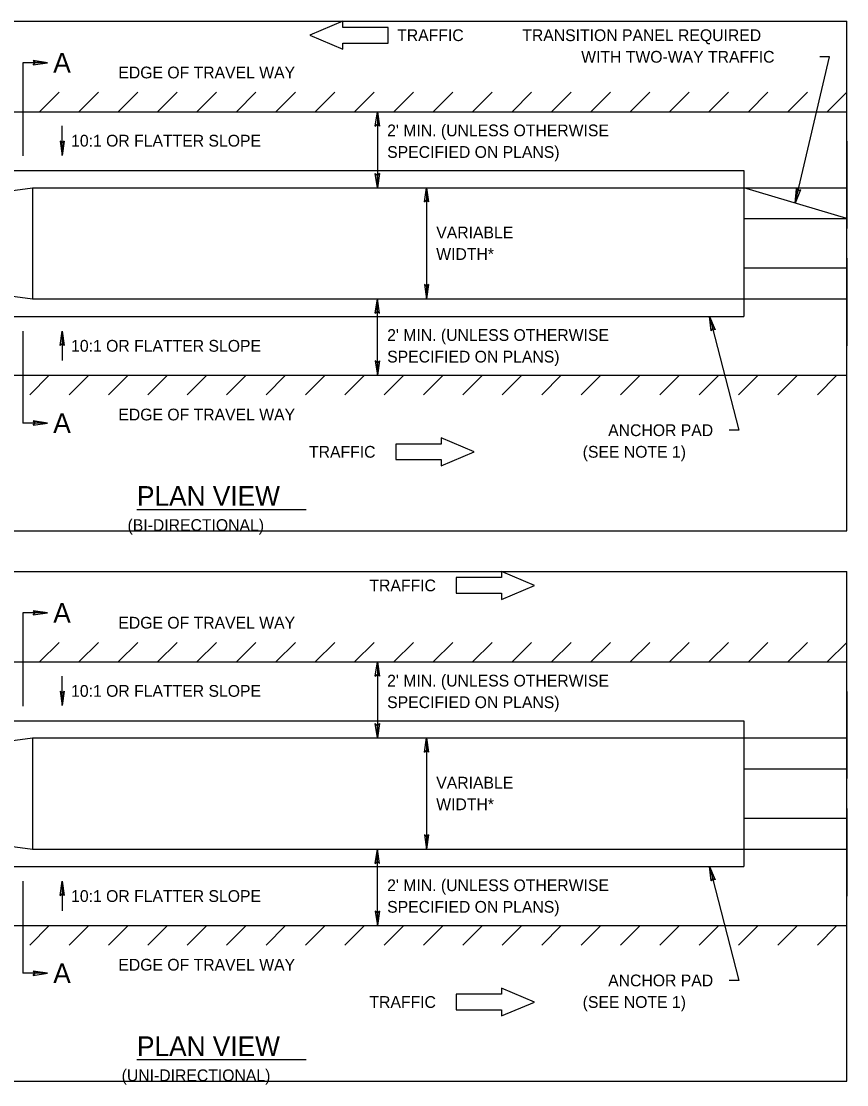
# Model space of a CAD drawing. Extents: x 12.3 to 19.6, y 6 to 16.1.
# Drawn here: x 15.05 to 19.25, y 10.66 to 16.08 of the extents above; entities that cross this region are included whole.
import ezdxf

# ---------------------------------------------------------------- set-up
doc = ezdxf.new("R2010")
doc.units = 0
for name, color, linetype in [('Default', 7, 'Continuous'), ('DETL-DIMS', 7, 'Continuous'), ('DETL-LINE', 7, 'Continuous'), ('DETL-NOTE', 7, 'Continuous'), ('DETL-TITL', 7, 'Continuous')]:
    doc.layers.add(name, color=color, linetype=linetype)

msp = doc.modelspace()

# ---------------------------------------------------------------- linework, layer by layer
at = {"layer": 'Default'}
for p, q in [((12.6137, 16.0809), (19.2537, 16.0809)), ((19.2537, 13.4842), (19.2537, 16.0809)), ((12.6137, 13.4842), (19.2537, 13.4842)), ((12.6137, 13.2777), (19.2537, 13.2777)), ((19.2537, 10.6809), (19.2537, 13.2777)), ((12.6137, 10.6809), (19.2537, 10.6809))]:
    msp.add_line(p, q, dxfattribs=at)
at = {"layer": 'DETL-DIMS'}
for p, q in [((15.1081, 15.8805), (15.181, 15.8699)), ((15.1081, 15.8805), (15.1172, 15.8699)), ((18.9915, 15.1544), (19.1665, 15.8999)), ((19.1665, 15.8999), (19.1165, 15.8999)), ((15.181, 15.8699), (15.056, 15.8699)), ((15.056, 15.8699), (15.056, 15.3949)), ((15.1081, 15.8593), (15.181, 15.8699)), ((15.1081, 15.8593), (15.1172, 15.8699)), ((16.8516, 15.547), (16.8622, 15.6199)), ((16.8622, 15.6199), (16.8622, 15.2331)), ((16.8728, 15.547), (16.8622, 15.6199)), ((16.8516, 15.547), (16.8622, 15.5561)), ((16.8728, 15.547), (16.8622, 15.5561)), ((15.256, 15.3975), (15.256, 15.5475)), ((15.2454, 15.4704), (15.256, 15.3975)), ((15.2454, 15.4704), (15.256, 15.4613)), ((15.2666, 15.4704), (15.256, 15.3975)), ((15.2666, 15.4704), (15.256, 15.4613)), ((16.8516, 15.306), (16.8622, 15.2331)), ((16.8516, 15.306), (16.8622, 15.2969)), ((16.8728, 15.306), (16.8622, 15.2331)), ((16.8728, 15.306), (16.8622, 15.2969)), ((17.1016, 15.1602), (17.1122, 15.2331)), ((17.1122, 15.2331), (17.1122, 14.6669)), ((17.1228, 15.1602), (17.1122, 15.2331)), ((18.9978, 15.2278), (18.9915, 15.1544)), ((18.9978, 15.2278), (19.0061, 15.2165)), ((19.0185, 15.2229), (18.9915, 15.1544)), ((19.0185, 15.2229), (19.0061, 15.2165)), ((17.1016, 15.1602), (17.1122, 15.1693)), ((17.1228, 15.1602), (17.1122, 15.1693)), ((17.1016, 14.7398), (17.1122, 14.6669)), ((17.1016, 14.7398), (17.1122, 14.7307)), ((17.1228, 14.7398), (17.1122, 14.6669)), ((17.1228, 14.7398), (17.1122, 14.7307)), ((16.8516, 14.594), (16.8622, 14.6669)), ((16.8728, 14.594), (16.8622, 14.6669)), ((16.8622, 14.2774), (16.8622, 14.6669)), ((16.8516, 14.594), (16.8622, 14.6031)), ((16.8728, 14.594), (16.8622, 14.6031)), ((18.5543, 14.5774), (18.7043, 13.9974)), ((18.5828, 14.5095), (18.5543, 14.5774)), ((18.5623, 14.5042), (18.5543, 14.5774)), ((15.056, 14.5024), (15.056, 14.0341)), ((15.2454, 14.4295), (15.256, 14.5024)), ((15.2666, 14.4295), (15.256, 14.5024)), ((15.256, 14.5024), (15.256, 14.3524)), ((18.5623, 14.5042), (18.5702, 14.5157)), ((18.5828, 14.5095), (18.5702, 14.5157)), ((15.2454, 14.4295), (15.256, 14.4386)), ((15.2666, 14.4295), (15.256, 14.4386)), ((16.8516, 14.3503), (16.8622, 14.2774)), ((16.8516, 14.3503), (16.8622, 14.3412)), ((16.8728, 14.3503), (16.8622, 14.2774)), ((16.8728, 14.3503), (16.8622, 14.3412)), ((15.181, 14.0341), (15.056, 14.0341)), ((15.1081, 14.0447), (15.181, 14.0341)), ((15.1081, 14.0447), (15.1172, 14.0341)), ((15.1081, 14.0235), (15.181, 14.0341)), ((15.1081, 14.0235), (15.1172, 14.0341)), ((18.7043, 13.9974), (18.6543, 13.9974)), ((15.181, 13.0667), (15.056, 13.0667)), ((15.056, 13.0667), (15.056, 12.5917)), ((15.1081, 13.0773), (15.181, 13.0667)), ((15.1081, 13.0773), (15.1172, 13.0667)), ((15.1081, 13.0561), (15.181, 13.0667)), ((15.1081, 13.0561), (15.1172, 13.0667)), ((16.8516, 12.7438), (16.8622, 12.8167)), ((16.8622, 12.8167), (16.8622, 12.4298)), ((16.8728, 12.7438), (16.8622, 12.8167)), ((15.256, 12.5943), (15.256, 12.7443)), ((16.8516, 12.7438), (16.8622, 12.7529)), ((16.8728, 12.7438), (16.8622, 12.7529)), ((15.2454, 12.6672), (15.256, 12.5943)), ((15.2454, 12.6672), (15.256, 12.6581)), ((15.2666, 12.6672), (15.256, 12.5943)), ((15.2666, 12.6672), (15.256, 12.6581)), ((16.8516, 12.5027), (16.8622, 12.4298)), ((16.8516, 12.5027), (16.8622, 12.4936)), ((16.8728, 12.5027), (16.8622, 12.4298)), ((16.8728, 12.5027), (16.8622, 12.4936)), ((17.1016, 12.3569), (17.1122, 12.4298)), ((17.1122, 12.4298), (17.1122, 11.8636)), ((17.1228, 12.3569), (17.1122, 12.4298)), ((17.1016, 12.3569), (17.1122, 12.366)), ((17.1228, 12.3569), (17.1122, 12.366)), ((17.1016, 11.9365), (17.1122, 11.8636)), ((17.1016, 11.9365), (17.1122, 11.9274)), ((17.1228, 11.9365), (17.1122, 11.8636)), ((17.1228, 11.9365), (17.1122, 11.9274)), ((16.8516, 11.7907), (16.8622, 11.8636)), ((16.8728, 11.7907), (16.8622, 11.8636)), ((16.8622, 11.4742), (16.8622, 11.8636)), ((16.8516, 11.7907), (16.8622, 11.7998)), ((16.8728, 11.7907), (16.8622, 11.7998)), ((18.5543, 11.7742), (18.7043, 11.1942)), ((18.5828, 11.7062), (18.5543, 11.7742)), ((18.5623, 11.7009), (18.5543, 11.7742)), ((18.5623, 11.7009), (18.5702, 11.7124)), ((18.5828, 11.7062), (18.5702, 11.7124)), ((15.056, 11.6992), (15.056, 11.2308)), ((15.2454, 11.6263), (15.256, 11.6992)), ((15.2666, 11.6263), (15.256, 11.6992)), ((15.256, 11.6992), (15.256, 11.5492)), ((15.2454, 11.6263), (15.256, 11.6354)), ((15.2666, 11.6263), (15.256, 11.6354)), ((16.8516, 11.5471), (16.8622, 11.4742)), ((16.8516, 11.5471), (16.8622, 11.538)), ((16.8728, 11.5471), (16.8622, 11.4742)), ((16.8728, 11.5471), (16.8622, 11.538)), ((15.181, 11.2308), (15.056, 11.2308)), ((15.1081, 11.2414), (15.181, 11.2308)), ((15.1081, 11.2414), (15.1172, 11.2308)), ((15.1081, 11.2202), (15.181, 11.2308)), ((15.1081, 11.2202), (15.1172, 11.2308)), ((18.7043, 11.1942), (18.6543, 11.1942))]:
    msp.add_line(p, q, dxfattribs=at)
for points in [[(16.9175, 16.0497), (16.686, 16.0497), (16.686, 16.0809), (16.5183, 16.0099), (16.686, 15.9389), (16.686, 15.9701), (16.9175, 15.9701), (16.9175, 16.0497)], [(16.9556, 13.8476), (17.1871, 13.8476), (17.1871, 13.8164), (17.3548, 13.8874), (17.1871, 13.9584), (17.1871, 13.9272), (16.9556, 13.9272), (16.9556, 13.8476)], [(17.2634, 13.1669), (17.4949, 13.1669), (17.4949, 13.1357), (17.6626, 13.2067), (17.4949, 13.2777), (17.4949, 13.2465), (17.2634, 13.2465), (17.2634, 13.1669)], [(17.2634, 11.0444), (17.4949, 11.0444), (17.4949, 11.0132), (17.6626, 11.0842), (17.4949, 11.1552), (17.4949, 11.124), (17.2634, 11.124), (17.2634, 11.0444)]]:
    msp.add_lwpolyline(points, dxfattribs=at)
for points in [[(15.1081, 15.8593), (15.181, 15.8699), (15.1081, 15.8805), (15.1172, 15.8699)], [(16.8516, 15.547), (16.8622, 15.6199), (16.8728, 15.547), (16.8622, 15.5561)], [(15.2454, 15.4704), (15.256, 15.3975), (15.2666, 15.4704), (15.256, 15.4613)], [(16.8728, 15.306), (16.8622, 15.2331), (16.8516, 15.306), (16.8622, 15.2969)], [(17.1016, 15.1602), (17.1122, 15.2331), (17.1228, 15.1602), (17.1122, 15.1693)], [(19.0185, 15.2229), (18.9915, 15.1544), (18.9978, 15.2278), (19.0061, 15.2165)], [(17.1016, 14.7398), (17.1122, 14.6669), (17.1228, 14.7398), (17.1122, 14.7307)], [(16.8728, 14.594), (16.8622, 14.6669), (16.8516, 14.594), (16.8622, 14.6031)], [(18.5623, 14.5042), (18.5543, 14.5774), (18.5828, 14.5095), (18.5702, 14.5157)], [(15.2454, 14.4295), (15.256, 14.5024), (15.2666, 14.4295), (15.256, 14.4386)], [(16.8516, 14.3503), (16.8622, 14.2774), (16.8728, 14.3503), (16.8622, 14.3412)], [(15.1081, 14.0235), (15.181, 14.0341), (15.1081, 14.0447), (15.1172, 14.0341)], [(15.1081, 13.0561), (15.181, 13.0667), (15.1081, 13.0773), (15.1172, 13.0667)], [(16.8516, 12.7438), (16.8622, 12.8167), (16.8728, 12.7438), (16.8622, 12.7529)], [(15.2454, 12.6672), (15.256, 12.5943), (15.2666, 12.6672), (15.256, 12.6581)], [(16.8728, 12.5027), (16.8622, 12.4298), (16.8516, 12.5027), (16.8622, 12.4936)], [(17.1016, 12.3569), (17.1122, 12.4298), (17.1228, 12.3569), (17.1122, 12.366)], [(17.1016, 11.9365), (17.1122, 11.8636), (17.1228, 11.9365), (17.1122, 11.9274)], [(16.8728, 11.7907), (16.8622, 11.8636), (16.8516, 11.7907), (16.8622, 11.7998)], [(18.5623, 11.7009), (18.5543, 11.7742), (18.5828, 11.7062), (18.5702, 11.7124)], [(15.2454, 11.6263), (15.256, 11.6992), (15.2666, 11.6263), (15.256, 11.6354)], [(16.8516, 11.5471), (16.8622, 11.4742), (16.8728, 11.5471), (16.8622, 11.538)], [(15.1081, 11.2202), (15.181, 11.2308), (15.1081, 11.2414), (15.1172, 11.2308)]]:
    msp.add_lwpolyline(points, close=True, dxfattribs=at)
at = {"layer": 'DETL-LINE'}
for p, q in [((15.1406, 15.6199), (15.2406, 15.7199)), ((15.3412, 15.6199), (15.4412, 15.7199)), ((15.5419, 15.6199), (15.6419, 15.7199)), ((15.7425, 15.6199), (15.8425, 15.7199)), ((15.9432, 15.6199), (16.0432, 15.7199)), ((16.1439, 15.6199), (16.2439, 15.7199)), ((16.3445, 15.6199), (16.4445, 15.7199)), ((16.5452, 15.6199), (16.6452, 15.7199)), ((16.7458, 15.6199), (16.8458, 15.7199)), ((16.9465, 15.6199), (17.0465, 15.7199)), ((17.1471, 15.6199), (17.2471, 15.7199)), ((17.3478, 15.6199), (17.4478, 15.7199)), ((17.5484, 15.6199), (17.6484, 15.7199)), ((17.7491, 15.6199), (17.8491, 15.7199)), ((17.9498, 15.6199), (18.0498, 15.7199)), ((18.1504, 15.6199), (18.2504, 15.7199)), ((18.3511, 15.6199), (18.4511, 15.7199)), ((18.5517, 15.6199), (18.6517, 15.7199)), ((18.7524, 15.6199), (18.8524, 15.7199)), ((18.953, 15.6199), (19.053, 15.7199)), ((19.1537, 15.6199), (19.2537, 15.7199)), ((12.8837, 15.6199), (19.2537, 15.6199)), ((19.2537, 15.4699), (19.2537, 15.0257)), ((14.4574, 15.3199), (18.7293, 15.3199)), ((18.7293, 15.3199), (18.7293, 14.5774)), ((14.5945, 15.1649), (15.106, 15.2331)), ((15.106, 15.2331), (19.2537, 15.2331)), ((15.106, 15.2331), (15.106, 14.6669)), ((19.2537, 15.0757), (18.7293, 15.2331)), ((18.7293, 15.0757), (19.2537, 15.0757)), ((19.2537, 14.8743), (19.2537, 14.4274)), ((18.7293, 14.8243), (19.2537, 14.8243)), ((14.5945, 14.7351), (15.106, 14.6669)), ((15.106, 14.6669), (19.2537, 14.6669)), ((14.4574, 14.5774), (18.7293, 14.5774)), ((12.8837, 14.2774), (19.2537, 14.2774)), ((15.0909, 14.1774), (15.1909, 14.2774)), ((15.2916, 14.1774), (15.3916, 14.2774)), ((15.4922, 14.1774), (15.5922, 14.2774)), ((15.6929, 14.1774), (15.7929, 14.2774)), ((15.8935, 14.1774), (15.9935, 14.2774)), ((16.0942, 14.1774), (16.1942, 14.2774)), ((16.2949, 14.1774), (16.3949, 14.2774)), ((16.4955, 14.1774), (16.5955, 14.2774)), ((16.6962, 14.1774), (16.7962, 14.2774)), ((16.8968, 14.1774), (16.9968, 14.2774)), ((17.0975, 14.1774), (17.1975, 14.2774)), ((17.2981, 14.1774), (17.3981, 14.2774)), ((17.4988, 14.1774), (17.5988, 14.2774)), ((17.6995, 14.1774), (17.7995, 14.2774)), ((17.9001, 14.1774), (18.0001, 14.2774)), ((18.1008, 14.1774), (18.2008, 14.2774)), ((18.3014, 14.1774), (18.4014, 14.2774)), ((18.5021, 14.1774), (18.6021, 14.2774)), ((18.7027, 14.1774), (18.8027, 14.2774)), ((18.9034, 14.1774), (19.0034, 14.2774)), ((19.1041, 14.1774), (19.2041, 14.2774)), ((15.1406, 12.8167), (15.2406, 12.9167)), ((15.3412, 12.8167), (15.4412, 12.9167)), ((15.5419, 12.8167), (15.6419, 12.9167)), ((15.7425, 12.8167), (15.8425, 12.9167)), ((15.9432, 12.8167), (16.0432, 12.9167)), ((16.1439, 12.8167), (16.2439, 12.9167)), ((16.3445, 12.8167), (16.4445, 12.9167)), ((16.5452, 12.8167), (16.6452, 12.9167)), ((16.7458, 12.8167), (16.8458, 12.9167)), ((16.9465, 12.8167), (17.0465, 12.9167)), ((17.1471, 12.8167), (17.2471, 12.9167)), ((17.3478, 12.8167), (17.4478, 12.9167)), ((17.5484, 12.8167), (17.6484, 12.9167)), ((17.7491, 12.8167), (17.8491, 12.9167)), ((17.9498, 12.8167), (18.0498, 12.9167)), ((18.1504, 12.8167), (18.2504, 12.9167)), ((18.3511, 12.8167), (18.4511, 12.9167)), ((18.5517, 12.8167), (18.6517, 12.9167)), ((18.7524, 12.8167), (18.8524, 12.9167)), ((18.953, 12.8167), (19.053, 12.9167)), ((19.1537, 12.8167), (19.2537, 12.9167)), ((12.8837, 12.8167), (19.2537, 12.8167)), ((19.2537, 12.6667), (19.2537, 12.2224)), ((14.4574, 12.5167), (18.7293, 12.5167)), ((18.7293, 12.5167), (18.7293, 11.7742)), ((14.5945, 12.3616), (15.106, 12.4298)), ((15.106, 12.4298), (19.2537, 12.4298)), ((15.106, 12.4298), (15.106, 11.8636)), ((18.7293, 12.2724), (19.2537, 12.2724)), ((19.2537, 12.071), (19.2537, 11.6242)), ((18.7293, 12.021), (19.2537, 12.021)), ((14.5945, 11.9318), (15.106, 11.8636)), ((15.106, 11.8636), (19.2537, 11.8636)), ((14.4574, 11.7742), (18.7293, 11.7742)), ((12.8837, 11.4742), (19.2537, 11.4742)), ((15.0909, 11.3742), (15.1909, 11.4742)), ((15.2916, 11.3742), (15.3916, 11.4742)), ((15.4922, 11.3742), (15.5922, 11.4742)), ((15.6929, 11.3742), (15.7929, 11.4742)), ((15.8935, 11.3742), (15.9935, 11.4742)), ((16.0942, 11.3742), (16.1942, 11.4742)), ((16.2949, 11.3742), (16.3949, 11.4742)), ((16.4955, 11.3742), (16.5955, 11.4742)), ((16.6962, 11.3742), (16.7962, 11.4742)), ((16.8968, 11.3742), (16.9968, 11.4742)), ((17.0975, 11.3742), (17.1975, 11.4742)), ((17.2981, 11.3742), (17.3981, 11.4742)), ((17.4988, 11.3742), (17.5988, 11.4742)), ((17.6995, 11.3742), (17.7995, 11.4742)), ((17.9001, 11.3742), (18.0001, 11.4742)), ((18.1008, 11.3742), (18.2008, 11.4742)), ((18.3014, 11.3742), (18.4014, 11.4742)), ((18.5021, 11.3742), (18.6021, 11.4742)), ((18.7027, 11.3742), (18.8027, 11.4742)), ((18.9034, 11.3742), (19.0034, 11.4742)), ((19.1041, 11.3742), (19.2041, 11.4742))]:
    msp.add_line(p, q, dxfattribs=at)
at = {"layer": 'DETL-TITL'}
for p, q in [((15.6375, 13.5942), (16.4999, 13.5942)), ((15.6375, 10.7909), (16.4999, 10.7909))]:
    msp.add_line(p, q, dxfattribs=at)

# ---------------------------------------------------------------- texts
at = {"layer": 'DETL-NOTE'}
for s, p in [('TRAFFIC', (16.9633, 15.9799)), ('10:1 OR FLATTER SLOPE', (15.3018, 15.4425)), ('TRAFFIC', (16.5141, 13.8574)), ('TRAFFIC', (16.8219, 13.1767)), ('10:1 OR FLATTER SLOPE', (15.3018, 12.6393)), ('TRAFFIC', (16.8219, 11.0542))]:
    msp.add_text(s, height=0.06, dxfattribs=at).set_placement(p)
for s, p in [('TRANSITION PANEL REQUIRED', (17.6006, 15.9799)), ('WITH TWO-WAY TRAFFIC', (17.9008, 15.8699)), ('EDGE OF TRAVEL WAY', (15.5426, 15.7899)), ("2' MIN. (UNLESS OTHERWISE", (16.9122, 15.4949)), ('SPECIFIED ON PLANS)', (16.9122, 15.3849)), ('VARIABLE', (17.1622, 14.975)), ('WIDTH*', (17.1622, 14.865)), ("2' MIN. (UNLESS OTHERWISE", (16.9122, 14.4524)), ('10:1 OR FLATTER SLOPE', (15.3018, 14.3974)), ('SPECIFIED ON PLANS)', (16.9122, 14.3424)), ('EDGE OF TRAVEL WAY', (15.5426, 14.0474)), ('ANCHOR PAD', (18.0382, 13.9674)), ('(SEE NOTE 1)', (17.9084, 13.8574)), ('(BI-DIRECTIONAL)', (15.5894, 13.4842)), ('EDGE OF TRAVEL WAY', (15.5426, 12.9867)), ("2' MIN. (UNLESS OTHERWISE", (16.9122, 12.6917)), ('SPECIFIED ON PLANS)', (16.9122, 12.5817)), ('VARIABLE', (17.1622, 12.1717)), ('WIDTH*', (17.1622, 12.0617)), ("2' MIN. (UNLESS OTHERWISE", (16.9122, 11.6492)), ('10:1 OR FLATTER SLOPE', (15.3018, 11.5942)), ('SPECIFIED ON PLANS)', (16.9122, 11.5392)), ('EDGE OF TRAVEL WAY', (15.5426, 11.2442)), ('ANCHOR PAD', (18.0382, 11.1642)), ('(SEE NOTE 1)', (17.9084, 11.0542)), ('(UNI-DIRECTIONAL)', (15.5594, 10.6809))]:
    msp.add_text(s, height=0.06, rotation=360, dxfattribs=at).set_placement(p)
at = {"layer": 'DETL-TITL'}
for s, p in [('A', (15.211, 15.8199)), ('A', (15.211, 13.9841)), ('PLAN VIEW', (15.6375, 13.6125)), ('A', (15.211, 13.0167)), ('A', (15.211, 11.1808)), ('PLAN VIEW', (15.6375, 10.8092))]:
    msp.add_text(s, height=0.1, rotation=360, dxfattribs=at).set_placement(p)

doc.saveas('drawing.dxf')
